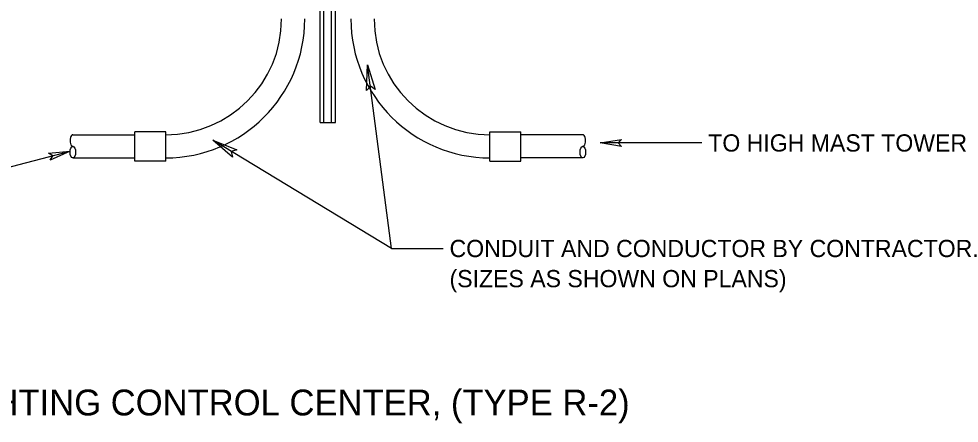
# Model space of a CAD drawing. Extents: x 99992 to 113392, y 99794 to 102182.
# Drawn here: x 111662 to 112316, y 100991 to 101273 of the extents above; entities that cross this region are included whole.
import ezdxf

# ---------------------------------------------------------------- set-up
doc = ezdxf.new("R2010")
doc.units = 0
doc.layers.add('Border Organizer Shape', color=7, linetype='Continuous')

msp = doc.modelspace()

# ---------------------------------------------------------------- linework, layer by layer
at = {"layer": 'Border Organizer Shape'}
for p, q in [((111871.7, 101201.03), (111871.7, 101905.42)), ((111882.45, 101201.03), (111882.45, 101905.42)), ((111874.39, 101201.03), (111874.39, 101486.01)), ((111879.77, 101201.03), (111879.77, 101486.01)), ((111921.51, 101113.21), (111904.76, 101241.21)), ((111871.7, 101201.03), (111882.45, 101201.03)), ((111699.71, 101192.44), (111742.82, 101192.44)), ((111764.32, 101194.57), (111742.82, 101194.57)), ((111742.82, 101174.08), (111742.82, 101194.57)), ((111764.32, 101174.08), (111764.32, 101194.57)), ((111921.51, 101113.21), (111797.13, 101188.56)), ((111989.95, 101174.08), (111989.95, 101194.57)), ((111989.95, 101194.57), (112011.46, 101194.57)), ((112011.46, 101174.08), (112011.46, 101194.57)), ((112054.56, 101192.44), (112011.46, 101192.44)), ((112137.38, 101186.72), (112066.59, 101186.72)), ((111581.08, 101150.58), (111697.78, 101180.98)), ((111699.71, 101176.3), (111742.82, 101176.3)), ((112054.56, 101176.3), (112011.46, 101176.3)), ((111764.32, 101174.08), (111742.82, 101174.08)), ((111989.95, 101174.08), (112011.46, 101174.08)), ((111921.51, 101113.21), (111957.36, 101113.21))]:
    msp.add_line(p, q, dxfattribs=at)
for points in [[(111904.07, 101223.15), (111904.76, 101241.21), (111910.07, 101223.94), (111906.71, 101226.32)], [(111810.8, 101176.74), (111797.13, 101188.56), (111813.93, 101181.91), (111809.97, 101180.78)], [(112081.44, 101184.22), (112066.59, 101186.72), (112081.44, 101189.22), (112079.09, 101186.72)], [(111682.78, 101179.66), (111697.78, 101180.98), (111684.04, 101174.82), (111685.68, 101177.83)]]:
    msp.add_lwpolyline(points, close=True, dxfattribs=at)
for centre, radius, start, end in [((111764.28, 101273.09), 80.66, 270, 0), ((111764.28, 101273.09), 96.79, 270, 0), ((111989.99, 101273.09), 96.79, 180, 270), ((111989.99, 101273.09), 80.66, 180, 270)]:
    msp.add_arc(centre, radius, start, end, dxfattribs=at)
for centre, start_param, end_param in [((111699.71, 101188.4), 6.264373, 9.469884), ((112054.56, 101188.4), 3.096486, 6.301998)]:
    msp.add_ellipse(centre, major_axis=(0, 4.03), ratio=0.485603, start_param=start_param, end_param=end_param, dxfattribs=at)
for centre in [(111699.71, 101180.34), (112054.56, 101180.34)]:
    msp.add_ellipse(centre, major_axis=(0, 4.03), ratio=0.485603, dxfattribs=at)

# ---------------------------------------------------------------- texts
for s, height, p in [(' TO HIGH MAST TOWER LIGHTS ', 12, (112137.38, 101180.72)), (' CONDUIT AND CONDUCTOR BY CONTRACTOR.', 12, (111957.36, 101107.21)), (' (SIZES AS SHOWN ON PLANS)', 12, (111957.36, 101086.21)), ('LIGHTING CONTROL CENTER, (TYPE R-2)', 18, (111605.7, 100996.91))]:
    msp.add_text(s, height=height, dxfattribs=at).set_placement(p)

doc.saveas('drawing.dxf')
